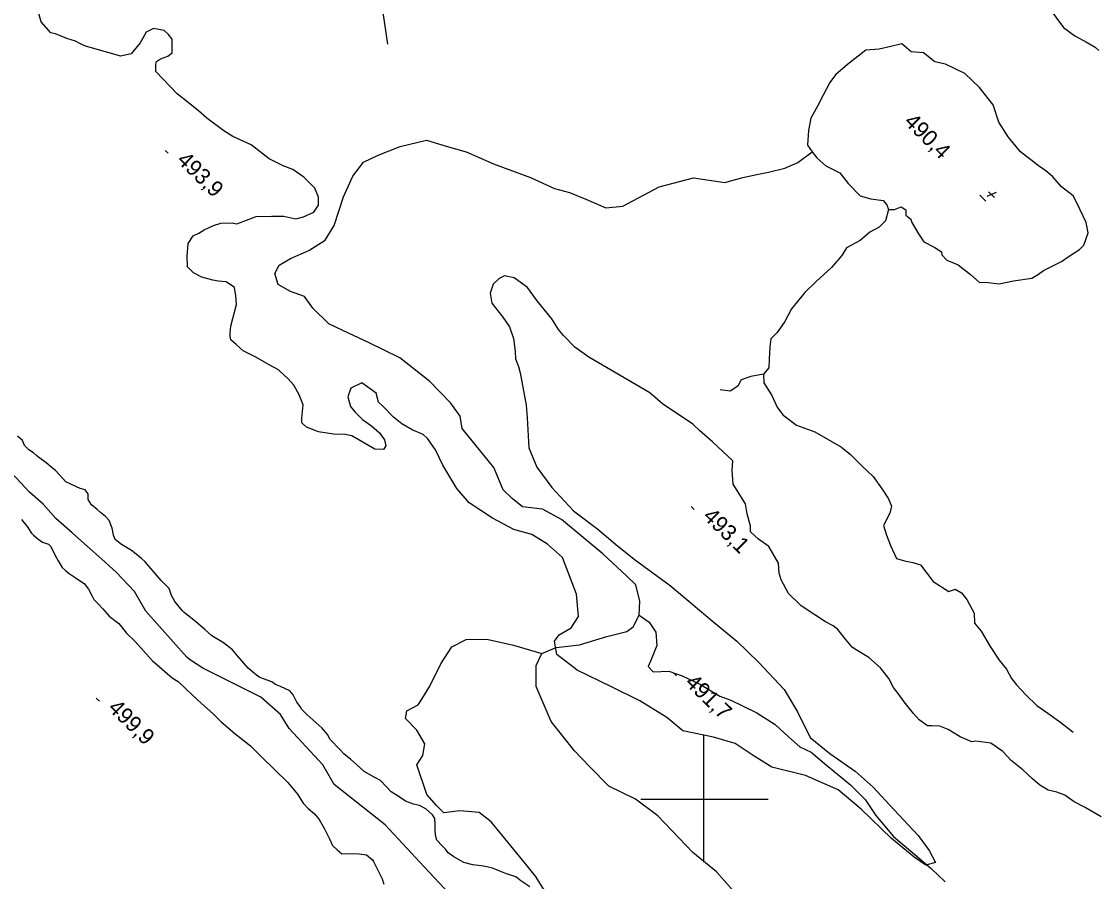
# Model space of a CAD drawing. Extents: x 642515 to 647219, y 6080136 to 6084356.
# Drawn here: x 643071.4 to 643274.3, y 6081784.5 to 6081946.7 of the extents above; entities that cross this region are included whole.
import ezdxf

# ---------------------------------------------------------------- set-up
doc = ezdxf.new("R2010")
doc.units = 0
for name, color, linetype in [('Level 1', 7, 'Continuous'), ('Level 2', 7, 'Continuous'), ('Level 22', 7, 'Continuous'), ('Level 3', 7, 'Continuous'), ('Level 4', 7, 'Continuous'), ('Level 61', 7, 'Continuous')]:
    doc.layers.add(name, color=color, linetype=linetype)

msp = doc.modelspace()

# ---------------------------------------------------------------- linework, layer by layer
at = {"layer": 'Level 1'}
msp.add_lwpolyline([(643265.17, 6081949.26), (643267.89, 6081945.63), (643270, 6081944.07), (643272.33, 6081942.76), (643273.84, 6081941.88), (643274.52, 6081941.28)], dxfattribs=at)
at = {"layer": 'Level 2'}
for points in [[(643108.49, 6081897.75), (643107.43, 6081897.93), (643105.38, 6081898.53), (643103.8, 6081899.32), (643102.69, 6081900.46), (643102.64, 6081902.47), (643102.82, 6081904.9), (643103.77, 6081906.33), (643104.79, 6081906.79), (643105.8, 6081907.42), (643107.6, 6081908.25), (643108.93, 6081908.73), (643111.1, 6081908.78), (643112, 6081908.6), (643114.28, 6081909.46), (643115.61, 6081909.94), (643118.58, 6081910.04), (643120.84, 6081910.02), (643123.12, 6081909.51), (643124.54, 6081909.92), (643126.5, 6081910.76), (643127.38, 6081912.1), (643127.37, 6081913.63), (643126.7, 6081915.28), (643124.64, 6081917.41), (643122.54, 6081918.82), (643120.73, 6081919.52), (643118.08, 6081920.81), (643114.7, 6081923.5), (643111.22, 6081925.06), (643109.55, 6081926.09), (643106.35, 6081928.48), (643104.73, 6081929.91), (643102.78, 6081931.48), (643100.75, 6081933.13), (643096.71, 6081937.32), (643096.71, 6081938.69), (643096.84, 6081939.18), (643097.61, 6081939.71), (643098.95, 6081940.2), (643099.8, 6081940.81), (643099.77, 6081942.5), (643099.8, 6081943.39), (643099.1, 6081944.31), (643098.25, 6081945.07), (643096.29, 6081945.43), (643094.89, 6081944.7), (643094.23, 6081943.62), (643093.73, 6081942.7), (643092.08, 6081940.67), (643090.02, 6081940.22), (643088.79, 6081940.55), (643087.24, 6081941.02), (643083.47, 6081942.08), (643082.48, 6081942.51), (643081.56, 6081943.02), (643079.92, 6081943.56), (643077.78, 6081944.4), (643076.88, 6081944.59), (643075.07, 6081946.65), (643074.55, 6081948.47)], [(643155.78, 6081855.97), (643153.44, 6081858.65), (643150.83, 6081863.08), (643149.45, 6081865.98), (643147.95, 6081868.06), (643147.1, 6081868.82), (643147.1, 6081868.82), (643145.03, 6081869.74), (643143.12, 6081870.83), (643141.51, 6081872.11), (643139.53, 6081874.16), (643138.68, 6081874.92), (643138.25, 6081876.66), (643135.56, 6081878.6), (643133.45, 6081877.58), (643132.91, 6081875.94), (643133.43, 6081874.12), (643134.21, 6081873.12), (643135.67, 6081871.67), (643137.35, 6081870.49), (643138.88, 6081869.13), (643139.85, 6081867.82), (643140.08, 6081866.7), (643139.64, 6081866.03), (643138.02, 6081866.09), (643133.69, 6081868.57), (643132.39, 6081868.82), (643130.21, 6081868.93), (643127.37, 6081869.32), (643125.14, 6081870.23), (643124.21, 6081871.06), (643124.23, 6081871.95), (643124.48, 6081874.46), (643123.72, 6081876.35), (643122.72, 6081878.14), (643121.68, 6081879.37), (643120.07, 6081880.8), (643119.81, 6081881.03), (643118.06, 6081881.97), (643115.56, 6081883.43), (643113.15, 6081884.65), (643111.88, 6081885.79), (643110.86, 6081886.69), (643110.73, 6081887.41), (643110.69, 6081888.05), (643110.86, 6081889.27), (643111.25, 6081890.74), (643111.89, 6081893.36), (643111.79, 6081894.97), (643111.53, 6081896.56), (643109.94, 6081897.67), (643108.49, 6081897.75)], [(643274.95, 6081796.73), (643271.95, 6081798.48), (643269.87, 6081799.56), (643268.1, 6081800.82), (643266.62, 6081801.38), (643264.99, 6081801.76), (643263.41, 6081802.71), (643262.05, 6081803.92), (643260.18, 6081805.58), (643257.98, 6081807.38), (643256.42, 6081809.06), (643254.16, 6081810.61), (643251.32, 6081811), (643250.61, 6081810.88), (643248.38, 6081811.79), (643246.12, 6081813.18), (643244.56, 6081813.81), (643243.11, 6081813.89), (643242.22, 6081813.91), (643240.63, 6081815.02), (643239.58, 6081816.25), (643237.84, 6081818.4), (643236.7, 6081820.02), (643235.83, 6081821.1), (643234.92, 6081822.82), (643233.35, 6081824.82), (643231.14, 6081826.78), (643228.46, 6081828.39), (643228.04, 6081828.76), (643226.74, 6081830.22), (643225.34, 6081832.06), (643224.42, 6081832.73), (643223, 6081833.53), (643221.16, 6081834.71), (643218.39, 6081836.56), (643216, 6081838.83), (643214.64, 6081841.41), (643214.24, 6081842.67), (643214.12, 6081844.6), (643212.32, 6081847.71), (643210.38, 6081849.12), (643208.85, 6081850.48), (643208.87, 6081851.53), (643208.24, 6081853.91), (643207.88, 6081855.74), (643205.56, 6081859.47), (643205.4, 6081862.03), (643205.53, 6081863.9), (643201.69, 6081867.45), (643199.31, 6081869.56), (643197.95, 6081870.77), (643192.25, 6081874.61), (643189.86, 6081876.72), (643178.36, 6081883.44), (643175.75, 6081885.3), (643173.6, 6081887.5), (643172.65, 6081888.65), (643171.4, 6081890.67), (643168.62, 6081894.05), (643166.77, 6081896.6), (643164.25, 6081898.38), (643162.46, 6081898.75), (643161.44, 6081898.29), (643160.3, 6081897.17), (643159.76, 6081895.53), (643160.04, 6081893.61), (643162.13, 6081891), (643163.37, 6081889.14), (643164.15, 6081886.93), (643164.46, 6081884.53), (643164.55, 6081883.09), (643165.12, 6081881.67), (643165.43, 6081880.48), (643166.54, 6081874.35), (643166.76, 6081872.02)], [(643166.76, 6081872.02), (643167.03, 6081866.32), (643168.54, 6081862.7), (643171.36, 6081858.85), (643175.49, 6081854.42), (643180.04, 6081850.99), (643183.78, 6081847.83), (643187.16, 6081845.14), (643193.72, 6081840.38), (643196.86, 6081837.75), (643201.61, 6081833.69), (643206.27, 6081829.86), (643210.37, 6081825.92), (643215.2, 6081820.73), (643217.71, 6081816.53), (643220.1, 6081811.68), (643223.82, 6081808.69), (643228.61, 6081805.35), (643232.01, 6081802.33), (643235.97, 6081798.06), (643240.45, 6081793.18), (643242.55, 6081790.41), (643243.74, 6081788.14), (643241.92, 6081787.63), (643239.74, 6081789.11), (643235.42, 6081792.63), (643229.7, 6081798.16), (643225.37, 6081801.85), (643219.25, 6081804.54), (643212.89, 6081806.09), (643209.38, 6081808.29), (643205.94, 6081810.58), (643201.84, 6081811.78), (643196.06, 6081812.96), (643193.1, 6081815.44), (643188, 6081818.6), (643182.61, 6081821.25), (643176.14, 6081824.41), (643172.34, 6081827.32), (643171.86, 6081829.87), (643172.75, 6081831.05), (643175, 6081832.4), (643176.4, 6081834.49), (643176.06, 6081838.74), (643173.38, 6081845.67), (643170.57, 6081848.16), (643167.64, 6081850), (643164.21, 6081850.92), (643160.22, 6081853.09), (643155.78, 6081855.97)], [(643084.56, 6081855.56), (643083.93, 6081856.56), (643083.97, 6081857.65), (643083.36, 6081858.42), (643082.46, 6081858.68), (643081.72, 6081858.95), (643080.55, 6081859.52), (643079.76, 6081859.91), (643077.81, 6081862.07), (643077.22, 6081862.52), (643076.03, 6081863.49), (643074.59, 6081864.6), (643074.25, 6081864.82), (643073.61, 6081865.38), (643072.73, 6081865.93), (643071.95, 6081866.76), (643071.72, 6081867.27), (643071.57, 6081867.7), (643070.59, 6081868.56)], [(643152.84, 6081781.37), (643146.48, 6081788.21), (643139.96, 6081795.21), (643130.35, 6081802.82), (643128.19, 6081806.55), (643121.84, 6081813.39), (643120.23, 6081816.03), (643116.5, 6081819.33), (643105.58, 6081824.78), (643103.08, 6081826.39), (643102.57, 6081826.85), (643097.4, 6081832.64), (643094.82, 6081835.53), (643092.66, 6081839.26), (643089.23, 6081842.91), (643086.51, 6081845.32), (643083.8, 6081847.72), (643080.92, 6081850.28), (643077.86, 6081852.99), (643075.45, 6081855.73), (643072.9, 6081857.99), (643069.47, 6081861.64)], [(643139.1, 6081803.58), (643137.85, 6081804.22), (643136.01, 6081805.31), (643134.52, 6081806.62), (643133.45, 6081807.55), (643132.18, 6081808.59), (643131.48, 6081809.35), (643129.54, 6081811.36), (643129.16, 6081812.22), (643128.03, 6081813.51), (643126.32, 6081815.01), (643125.17, 6081816.02), (643124.26, 6081816.97), (643123.94, 6081817.55), (643123.32, 6081818.39), (643122.63, 6081819.76), (643121.98, 6081820.48), (643120.2, 6081821.29), (643119.25, 6081821.67), (643118.57, 6081822.18), (643116.3, 6081823.04), (643115.67, 6081823.44), (643114.14, 6081824.79), (643112.09, 6081827.11), (643111.18, 6081828.22), (643109.48, 6081829.55), (643108.18, 6081830.31), (643107.26, 6081830.89), (643105.94, 6081832.06), (643104.57, 6081833.25), (643102.92, 6081834.55), (643102.06, 6081835.3), (643101.72, 6081835.6), (643100.28, 6081837.32), (643099.64, 6081838.48), (643099.19, 6081839.78), (643097.73, 6081841.29), (643094.72, 6081844.84), (643094.03, 6081845.44), (643093.01, 6081846.25), (643092.12, 6081846.96), (643090.2, 6081848.12), (643089.01, 6081849.01), (643088.71, 6081849.87), (643088.47, 6081851.15), (643087.89, 6081852.64), (643087.19, 6081853.4), (643086.26, 6081854.14), (643085.62, 6081854.7), (643084.56, 6081855.56)], [(643071.37, 6081852.82), (643072.46, 6081851.48), (643073.23, 6081850.21), (643073.65, 6081849.84), (643074.42, 6081849.16), (643075.3, 6081848.54), (643076.45, 6081848.14), (643076.83, 6081847.8), (643077.15, 6081847.22), (643077.66, 6081846.17), (643078.3, 6081845.01), (643079.07, 6081843.73), (643079.62, 6081843.25), (643080.34, 6081842.62), (643081.31, 6081842), (643082.15, 6081841.41), (643083.19, 6081840.72), (643084.02, 6081839.69), (643084.72, 6081838.33), (643085.04, 6081837.75), (643085.9, 6081836.84), (643086.72, 6081835.97), (643087.93, 6081834.61), (643089.71, 6081833.2), (643091.19, 6081831.38), (643092.73, 6081829.87), (643096.02, 6081826.24), (643099.76, 6081822.96), (643100.93, 6081822.23), (643102.48, 6081820.73), (643105.29, 6081818.11), (643107.51, 6081816.17), (643109.05, 6081814.66), (643111.6, 6081812.42), (643114.56, 6081810.13), (643115.42, 6081809.23), (643116.62, 6081808.02)], [(643116.62, 6081808.02), (643121.59, 6081803.21), (643123.42, 6081801.01), (643124.49, 6081799.31), (643125.44, 6081798.33), (643126.63, 6081797.29), (643127.51, 6081796.22), (643128.51, 6081794.44), (643129.43, 6081792.58), (643130, 6081791.33), (643130.93, 6081790.51), (643131.78, 6081789.77), (643132.74, 6081789.83), (643135.07, 6081789.74), (643136.44, 6081789.59), (643137.54, 6081788.62), (643137.73, 6081788.31), (643139.39, 6081785.05), (643139.7, 6081784.03)], [(643167.24, 6081783.51), (643165.55, 6081784.68), (643164.62, 6081785.43), (643162.85, 6081785.99), (643161.57, 6081786.51), (643160.17, 6081787.06), (643159.15, 6081787.28), (643158.05, 6081787.49), (643156.51, 6081787.71), (643154.76, 6081788.11), (643152.92, 6081789.2), (643151.86, 6081789.97), (643151.3, 6081790.62), (643150.73, 6081791.27), (643149.7, 6081792.33), (643149.47, 6081793.28), (643149.41, 6081794.24), (643149.41, 6081795.37), (643149.34, 6081796.41), (643148.85, 6081797.14), (643147.61, 6081798.23), (643146.44, 6081798.87), (643145.3, 6081799.12), (643143.78, 6081799.7), (643142.39, 6081800.62), (643141.09, 6081801.46), (643139.1, 6081803.58)]]:
    msp.add_lwpolyline(points, dxfattribs=at)
at = {"layer": 'Level 22'}
msp.add_lwpolyline([(643217.91, 6082043.54), (643216.42, 6082041.68), (643214.1, 6082038.8), (643210.16, 6082034.77), (643206.42, 6082031.48), (643203.7, 6082028.14), (643200.27, 6082024.26), (643197.54, 6082021.08), (643194.71, 6082017.36), (643192.14, 6082012.65), (643187.96, 6082006.11), (643183.94, 6081999.75), (643181.62, 6081996.18), (643178.58, 6081992.13), (643172.16, 6081984.01), (643167.44, 6081979.01), (643161.24, 6081973.96), (643153.72, 6081968.03), (643147.44, 6081962.89), (643141.51, 6081956.53), (643139.26, 6081950.11), (643140.37, 6081942.44)], dxfattribs=at)
at = {"layer": 'Level 3'}
for p, q in [((643098.47, 6081922.44), (643099.04, 6081921.88)), ((643252.11, 6081913.99), (643253.25, 6081912.86)), ((643255.18, 6081914.46), (643253.41, 6081913.73)), ((643253.74, 6081914.63), (643254.84, 6081913.53)), ((643197.67, 6081855.24), (643198.25, 6081854.68)), ((643194.32, 6081823.89), (643194.89, 6081823.33)), ((643085.48, 6081819.11), (643086.05, 6081818.55))]:
    msp.add_line(p, q, dxfattribs=at)
at = {"layer": 'Level 4'}
for points in [[(643270.73, 6081911.92), (643269.72, 6081913.83), (643267.51, 6081915.53), (643265.88, 6081917.42), (643264.48, 6081918.67), (643263.41, 6081919.35), (643259.77, 6081922.19), (643257.42, 6081925.02), (643255.69, 6081927.77), (643254.64, 6081931.05), (643252.03, 6081934.27), (643249.29, 6081936.92), (643245.6, 6081938.67), (643243.6, 6081939.15), (643241.44, 6081940.83), (643239.17, 6081941.02), (643237.39, 6081942.52), (643235.29, 6081942.03), (643233.1, 6081941.54), (643230.58, 6081941.35), (643227.12, 6081938.65), (643224.9, 6081936.67), (643223.78, 6081935.23), (643222.56, 6081932.83), (643221.48, 6081930.75), (643220.24, 6081928.51), (643219.78, 6081926.19), (643219.59, 6081923.4), (643220.49, 6081922.18), (643221.34, 6081921.01), (643223.05, 6081919.51), (643225.67, 6081918.17), (643227.24, 6081916.18), (643229.51, 6081913.86), (643231.52, 6081913.3), (643233.88, 6081912.96), (643234.53, 6081912.15), (643234.9, 6081911.29), (643236.03, 6081911.28), (643237.25, 6081911.79), (643238.13, 6081911.24), (643238.15, 6081910.24), (643239.08, 6081909.49), (643239.28, 6081908.86), (643240.54, 6081906.68), (643241.52, 6081905.21), (643243.6, 6081904.13), (643244.85, 6081903.32), (643244.93, 6081902.72), (643245.88, 6081901.73), (643247.98, 6081900.85), (643250.31, 6081899.02), (643251.97, 6081897.55), (643253.67, 6081897.49), (643255.73, 6081897.25), (643258.44, 6081897.82), (643261.91, 6081898.31), (643263.15, 6081899.1), (643264.12, 6081899.77), (643267.52, 6081901.46), (643268.91, 6081902.51), (643270.92, 6081903.75), (643271.72, 6081904.56), (643272.5, 6081906.9), (643272.14, 6081908.81), (643270.98, 6081911.36), (643270.73, 6081911.92)], [(643206.76, 6081781.44), (643202.44, 6081786.34), (643197.96, 6081790.01), (643191.34, 6081796.94), (643187.13, 6081800.06), (643182.16, 6081802.5), (643178.47, 6081806.22), (643175.64, 6081809.19), (643171.27, 6081814.73), (643168.45, 6081821.33), (643168.45, 6081825.27), (643169.52, 6081827.52), (643172.18, 6081828.64), (643176.57, 6081829.15), (643181.78, 6081830.76), (643185.5, 6081831.71), (643186.73, 6081832.59), (643187.88, 6081834.75), (643187.96, 6081837.42), (643187.21, 6081840.52), (643185.49, 6081842.18), (643180.98, 6081846.34), (643173.18, 6081852.8), (643169.6, 6081854.76), (643165.87, 6081855.18), (643163.93, 6081856.75), (643162.22, 6081858.42), (643160.43, 6081862.59), (643154.5, 6081869.97), (643154.12, 6081872.28), (643152.36, 6081874.75), (643148.4, 6081878.87), (643142.74, 6081883.28), (643136.93, 6081886.15), (643131.97, 6081888.43), (643129.31, 6081889.72), (643126.31, 6081892.69), (643124.73, 6081894.85), (643122.1, 6081895.82), (643119.76, 6081897.13), (643119.15, 6081899.19), (643119.94, 6081900.77), (643122.11, 6081902.03), (643125.56, 6081903.52), (643128.66, 6081905.48), (643130.34, 6081908.25), (643132.1, 6081913.67), (643133.87, 6081917.57), (643135.88, 6081920.19), (643138.61, 6081921.56), (643142.77, 6081923.18), (643147.77, 6081924.37), (643151.46, 6081923.23), (643155.22, 6081922.16), (643160.35, 6081919.89), (643167.35, 6081917.33), (643171.9, 6081915.27), (643174.69, 6081914.47), (643177.82, 6081913.21), (643181.55, 6081911.58), (643184.74, 6081911.93), (643191.6, 6081915.57), (643198.09, 6081917.25), (643204.01, 6081916.4), (643207.41, 6081917.33), (643210.03, 6081917.89), (643212.26, 6081918.35), (643215.35, 6081919.1), (643217.78, 6081920.13), (643220.49, 6081922.18)], [(643234.9, 6081911.29), (643234.31, 6081909.16), (643233.09, 6081907.96), (643231.34, 6081907.01), (643229.54, 6081905.42), (643226.97, 6081904.06), (643226.05, 6081902.6), (643224.13, 6081900.35), (643221.24, 6081897.68), (643219.11, 6081895.63), (643216.6, 6081892.54), (643215.33, 6081890.17), (643213.85, 6081888.07), (643212.67, 6081886.92), (643212.52, 6081885.38), (643212.34, 6081883.04), (643212.28, 6081881.42), (643211.3, 6081880.24), (643208.92, 6081879.78), (643207.1, 6081879.18), (643206.45, 6081877.94), (643205.02, 6081877.01), (643203.11, 6081877.26)], [(643211.28, 6081880.24), (643211.34, 6081878.59), (643212.9, 6081876.23), (643213.88, 6081874), (643214.93, 6081872.53), (643217.55, 6081870.6), (643220.97, 6081869.32), (643226.01, 6081866.44), (643227.7, 6081865.1), (643229.93, 6081862.9), (643231.98, 6081860.93), (643233.66, 6081858.54), (643234.9, 6081856.68), (643235.46, 6081855.35), (643235.1, 6081854), (643233.95, 6081851.68), (643234.51, 6081849.83), (643235.27, 6081847.94), (643236.35, 6081845.47), (643237.9, 6081845), (643239.45, 6081844.7), (643240.89, 6081844.26), (643242.11, 6081842.72), (643243.29, 6081841.15), (643246.23, 6081839.23), (643247.45, 6081839.67), (643248.61, 6081839.01), (643249.62, 6081837.75), (643251.02, 6081835.14), (643251.1, 6081833.25), (643252.36, 6081831.76), (643254.06, 6081828.89), (643255.75, 6081826.26), (643257.14, 6081824.57), (643258.09, 6081822.82), (643259.01, 6081821.63), (643260.74, 6081819.72), (643262.87, 6081817.76), (643264.89, 6081816.27), (643267.37, 6081814.53), (643269.7, 6081812.7)], [(643187.88, 6081834.75), (643189.74, 6081833.42), (643190.98, 6081831.56), (643191.21, 6081829.07), (643190.16, 6081826.51), (643189.53, 6081825.1), (643190.47, 6081824.11), (643193.44, 6081824.21), (643195.99, 6081823.32), (643199.39, 6081821.67), (643203.06, 6081819.48), (643205.12, 6081818.71), (643207.36, 6081817.64), (643210.01, 6081816.35), (643213.52, 6081814.15), (643216, 6081811.8), (643218.12, 6081809.91), (643220.28, 6081808.92), (643222.82, 6081806.81), (643227.73, 6081802.76), (643230.47, 6081800.03), (643232.51, 6081797.01), (643235.81, 6081793.02), (643239.46, 6081789.93), (643242.94, 6081787), (643245.58, 6081784.5)], [(643170.77, 6081781.65), (643168.28, 6081785.52), (643165.93, 6081788.52), (643163.67, 6081791.28), (643159.94, 6081795.8), (643157.66, 6081797.52), (643154.02, 6081797.86), (643150.99, 6081797.51), (643149.62, 6081798.88), (643147.81, 6081800.94), (643145.93, 6081806.55), (643147.03, 6081808.31), (643147.46, 6081810.51), (643145.93, 6081813.07), (643143.79, 6081815.28), (643144.02, 6081816.74), (643146.2, 6081817.84), (643146.86, 6081818.93), (643148.39, 6081821.36), (643150.46, 6081825.59), (643152.52, 6081828.77), (643155.25, 6081830.15), (643159.1, 6081830.22), (643164.16, 6081829.08), (643169.52, 6081827.52)]]:
    msp.add_lwpolyline(points, dxfattribs=at)
at = {"layer": 'Level 61'}
for p, q in [((643200, 6081812.16), (643200, 6081788.16)), ((643212.16, 6081800), (643188.16, 6081800))]:
    msp.add_line(p, q, dxfattribs=at)

# ---------------------------------------------------------------- texts
at = {"layer": 'Level 3'}
for s, rotation, p in [('  490,4', 315.1735, (643236.05, 6081929.22)), ('493,9', 315.59, (643100.5, 6081920.39)), ('493,1', 315.59, (643199.7, 6081853.2)), ('491,7', 315.59, (643196.34, 6081821.84)), ('499,9', 315.59, (643087.51, 6081817.07))]:
    msp.add_text(s, height=3, rotation=rotation, dxfattribs=at).set_placement(p)

doc.saveas('drawing.dxf')
